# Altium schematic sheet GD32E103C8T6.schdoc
size 127 x 101 mm
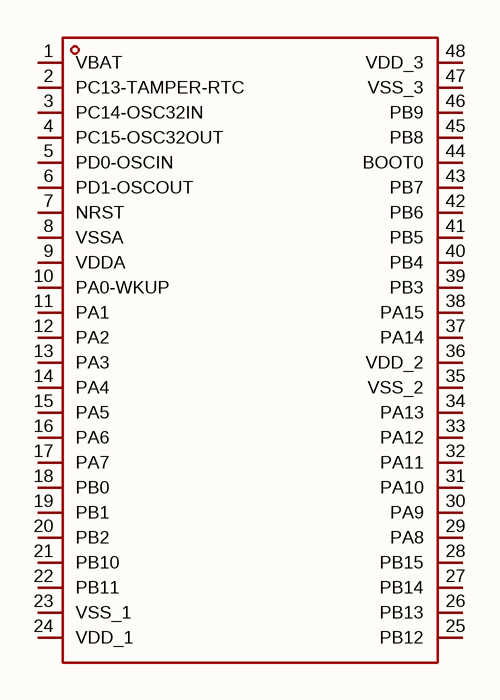
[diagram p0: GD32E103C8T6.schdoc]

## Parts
U?  gd32e103c8t6  [LQFP-48_L7.0-W7.0-P0.50-LS9.0-BL]  (value not drawn)

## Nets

Not connected (* = marked no-connect by the designer): U? 1(VBAT) 2(PC13-TAMPER-RTC) 3(PC14-OSC32IN) 4(PC15-OSC32OUT) 5(PD0-OSCIN) 6(PD1-OSCOUT) 7(NRST) 8(VSSA) 9(VDDA) 10(PA0-WKUP) 11(PA1) 12(PA2) 13(PA3) 14(PA4) 15(PA5) 16(PA6) 17(PA7) 18(PB0) 19(PB1) 20(PB2) 21(PB10) 22(PB11) 23(VSS_1) 24(VDD_1) 25(PB12) 26(PB13) 27(PB14) 28(PB15) 29(PA8) 30(PA9) 31(PA10) 32(PA11) 33(PA12) 34(PA13) 35(VSS_2) 36(VDD_2) 37(PA14) 38(PA15) 39(PB3) 40(PB4) 41(PB5) 42(PB6) 43(PB7) 44(BOOT0) 45(PB8) 46(PB9) 47(VSS_3) 48(VDD_3)

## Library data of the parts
U? = gd32e103c8t6: CPU内核:ARM-M4;CPU最大主频:120MHz;应用领域:-;; Manufacturer: GigaDevice(兆易创新); AddInBom: yes; ModelId: 093be70396ff421eb2cdb946d5311efc; ModelName: LQFP-48_L7.0-W7.0-H1.4-LS9.0-P0.50; ModelTransform: 354.331,354.331,0,0,0,0,0,0,0; CPU Core: ARM-M4; CPU Maximum Speed: 120MHz; Program Storage Size: 64KB; Program Memory Type: FLASH; Number of I/O: 37; ADC (Bit): 12bit; PWM (Bit): 16bit; Voltage - Supply: 1.71V~3.6V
